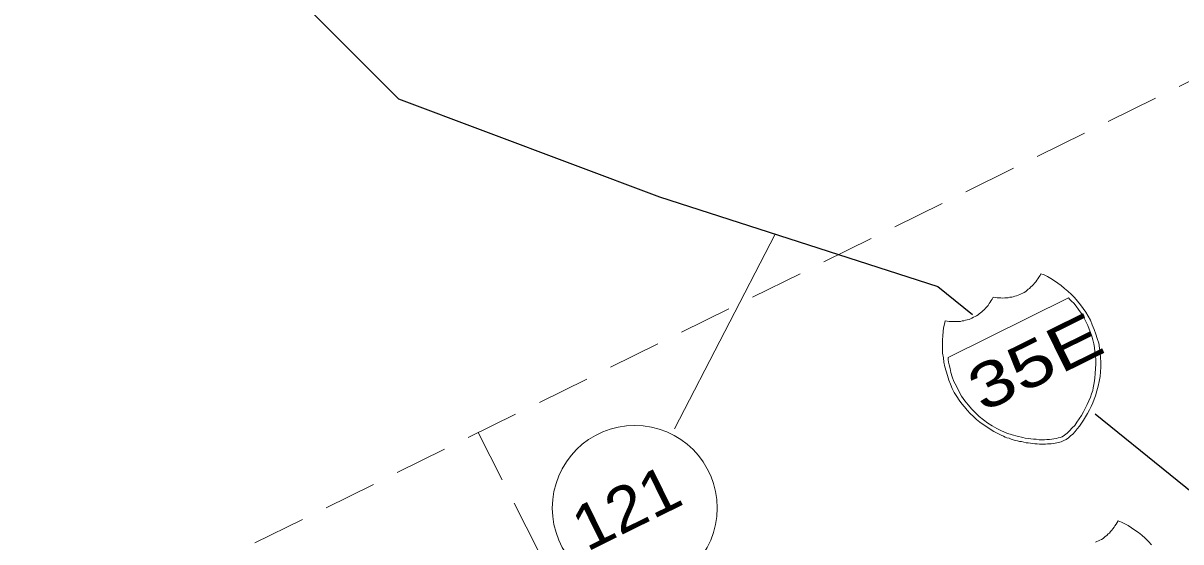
# Model space of a CAD drawing. Extents: x 2356606 to 2371222, y 6973096 to 6982644.
# Drawn here: x 2370920.3 to 2371051.8, y 6980586.9 to 6980645.7 of the extents above; entities that cross this region are included whole.
import ezdxf

# ---------------------------------------------------------------- set-up
doc = ezdxf.new("R2010")
doc.units = 0
doc.header["$LTSCALE"] = 2
doc.linetypes.add('MEDIUM_DASHED', pattern=[4.5, 3, -1.5])
doc.layers.add('62', color=7, linetype='Continuous', lineweight=13)
doc.layers.add('63', color=7, linetype='Continuous', lineweight=13)

msp = doc.modelspace()

# ---------------------------------------------------------------- linework, layer by layer
at = {"layer": '62', "linetype": 'MEDIUM_DASHED'}
for p, q in [((2371056.951, 6980641.227), (2370654.977, 6980442.841)), ((2370972, 6980599.301), (2371099.701, 6980348.989))]:
    msp.add_line(p, q, dxfattribs=at)
at = {"layer": '62'}
msp.add_line((2370994.27, 6980599.729), (2371005.707, 6980621.809), dxfattribs=at)
at = {"layer": '62', "lineweight": 25}
for points in [[(2370920.544, 6980679.674), (2370936.659, 6980663.489), (2370962.929, 6980637.158), (2370992.577, 6980626.045), (2371024.155, 6980615.857), (2371028.102, 6980612.689)], [(2371042.013, 6980601.435), (2371059.037, 6980587.681), (2371082.073, 6980558.75), (2371107.466, 6980541.874)]]:
    msp.add_lwpolyline(points, dxfattribs=at)
at = {"layer": '62'}
for points in [[(2371031.333, 6980614.584), (2371031.542, 6980614.563), (2371031.765, 6980614.572), (2371031.937, 6980614.581), (2371032.158, 6980614.59), (2371032.35, 6980614.658), (2371032.551, 6980614.657), (2371032.721, 6980614.718), (2371032.923, 6980614.765), (2371033.106, 6980614.807), (2371033.297, 6980614.875), (2371033.458, 6980614.955), (2371033.64, 6980615.044), (2371033.8, 6980615.122), (2371033.963, 6980615.203), (2371034.153, 6980615.324), (2371034.275, 6980615.434), (2371034.416, 6980615.554), (2371034.587, 6980615.664), (2371034.731, 6980615.833), (2371034.882, 6980615.934), (2371035.023, 6980616.104), (2371035.157, 6980616.244), (2371035.276, 6980616.405), (2371035.388, 6980616.586), (2371035.511, 6980616.747), (2371035.642, 6980616.935), (2371035.773, 6980617.126), (2371035.874, 6980617.327), (2371036.245, 6980617.185), (2371036.616, 6980616.991), (2371037, 6980616.777), (2371037.401, 6980616.525), (2371037.781, 6980616.261), (2371038.171, 6980615.976), (2371038.554, 6980615.662), (2371038.935, 6980615.35), (2371039.324, 6980614.964), (2371039.677, 6980614.611), (2371040.024, 6980614.206), (2371040.355, 6980613.793), (2371040.665, 6980613.369), (2371040.975, 6980612.944), (2371041.214, 6980612.509), (2371041.482, 6980612.066), (2371041.689, 6980611.541), (2371041.931, 6980611.006), (2371042.089, 6980610.482), (2371042.269, 6980609.969), (2371042.426, 6980609.443), (2371042.504, 6980608.879), (2371042.581, 6980608.364), (2371042.649, 6980607.82), (2371042.665, 6980607.277), (2371042.662, 6980606.723), (2371042.621, 6980606.2), (2371042.578, 6980605.678), (2371042.484, 6980605.104), (2371042.372, 6980604.573), (2371042.228, 6980604.05), (2371042.054, 6980603.486), (2371041.921, 6980603.096), (2371041.777, 6980602.673), (2371041.574, 6980602.272), (2371041.39, 6980601.88), (2371041.169, 6980601.469), (2371040.936, 6980601.078), (2371040.711, 6980600.716), (2371040.487, 6980600.356), (2371040.244, 6980600.036), (2371040.001, 6980599.715), (2371039.748, 6980599.414), (2371039.484, 6980599.132), (2371039.231, 6980598.934), (2371038.99, 6980598.712), (2371038.728, 6980598.534), (2371038.484, 6980598.413)], [(2371038.484, 6980598.413), (2371038.323, 6980598.334), (2371038.183, 6980598.264), (2371038.002, 6980598.224), (2371037.851, 6980598.174), (2371037.669, 6980598.136), (2371037.487, 6980598.097), (2371037.257, 6980598.057), (2371037.046, 6980598.029), (2371036.842, 6980598.03), (2371036.621, 6980598.021), (2371036.379, 6980598.001), (2371036.158, 6980597.992), (2371035.915, 6980597.974), (2371035.707, 6980597.995), (2371035.446, 6980598.018), (2371035.193, 6980598.019), (2371034.95, 6980598.05), (2371034.679, 6980598.092), (2371034.439, 6980598.123), (2371034.197, 6980598.153), (2371033.945, 6980598.206), (2371033.683, 6980598.277), (2371033.444, 6980598.31), (2371033.211, 6980598.369), (2371032.96, 6980598.422), (2371032.729, 6980598.483), (2371032.488, 6980598.565), (2371032.267, 6980598.657), (2371032.015, 6980598.709), (2371031.805, 6980598.779), (2371031.603, 6980598.88), (2371031.373, 6980598.994), (2371030.972, 6980599.196), (2371030.529, 6980599.43), (2371030.119, 6980599.704), (2371029.727, 6980599.938), (2371029.316, 6980600.211), (2371028.926, 6980600.494), (2371028.553, 6980600.789), (2371028.203, 6980601.143), (2371027.845, 6980601.466), (2371027.513, 6980601.831), (2371027.203, 6980602.206), (2371026.893, 6980602.581), (2371026.572, 6980602.974), (2371026.313, 6980603.399), (2371026.032, 6980603.863), (2371025.784, 6980604.316), (2371025.596, 6980604.801), (2371025.416, 6980605.265), (2371025.248, 6980605.76), (2371025.099, 6980606.264), (2371024.972, 6980606.777), (2371024.864, 6980607.301), (2371024.795, 6980607.794), (2371024.709, 6980608.329), (2371024.711, 6980608.832), (2371024.695, 6980609.325), (2371024.706, 6980609.806), (2371024.728, 6980610.271), (2371024.791, 6980610.753), (2371024.813, 6980611.166), (2371024.906, 6980611.586), (2371025.018, 6980611.97), (2371025.242, 6980611.928), (2371025.471, 6980611.915), (2371025.703, 6980611.906), (2371025.904, 6980611.905), (2371026.136, 6980611.892), (2371026.336, 6980611.893), (2371026.547, 6980611.921), (2371026.749, 6980611.92), (2371026.92, 6980611.98), (2371027.121, 6980611.979), (2371027.315, 6980612.048), (2371027.498, 6980612.087), (2371027.718, 6980612.148), (2371027.868, 6980612.196), (2371028.03, 6980612.276), (2371028.232, 6980612.376), (2371028.394, 6980612.456), (2371028.555, 6980612.535), (2371028.728, 6980612.646), (2371028.867, 6980612.765), (2371029.008, 6980612.883), (2371029.16, 6980612.986), (2371029.323, 6980613.166), (2371029.475, 6980613.266), (2371029.597, 6980613.424), (2371029.728, 6980613.567), (2371029.872, 6980613.736), (2371030, 6980613.927), (2371030.122, 6980614.087), (2371030.236, 6980614.268), (2371030.345, 6980614.448), (2371030.467, 6980614.659), (2371030.688, 6980614.617), (2371030.901, 6980614.596), (2371031.132, 6980614.585), (2371031.333, 6980614.584)], [(2371042.059, 6980586.855), (2371042.22, 6980586.934), (2371042.4, 6980587.023), (2371042.562, 6980587.102), (2371042.744, 6980587.193), (2371042.918, 6980587.302), (2371043.057, 6980587.421), (2371043.179, 6980587.531), (2371043.35, 6980587.642), (2371043.491, 6980587.812), (2371043.643, 6980587.912), (2371043.784, 6980588.081), (2371043.915, 6980588.223), (2371044.037, 6980588.383), (2371044.17, 6980588.574), (2371044.272, 6980588.723), (2371044.403, 6980588.915), (2371044.535, 6980589.104), (2371044.636, 6980589.306), (2371045.007, 6980589.16), (2371045.38, 6980588.97), (2371045.76, 6980588.756), (2371046.162, 6980588.502), (2371046.544, 6980588.238), (2371046.933, 6980587.956), (2371047.335, 6980587.651), (2371047.696, 6980587.327), (2371048.087, 6980586.942), (2371048.435, 6980586.589)]]:
    msp.add_lwpolyline(points, dxfattribs=at)
msp.add_lwpolyline([(2371038.99, 6980614.574), (2371025.328, 6980607.831), (2371025.348, 6980607.591), (2371025.388, 6980607.308), (2371025.446, 6980606.986), (2371025.555, 6980606.563), (2371025.653, 6980606.109), (2371025.791, 6980605.627), (2371025.998, 6980605.103), (2371026.27, 6980604.558), (2371026.545, 6980603.991), (2371026.867, 6980603.448), (2371027.227, 6980602.921), (2371027.616, 6980602.436), (2371028.018, 6980601.978), (2371028.428, 6980601.553), (2371028.867, 6980601.12), (2371029.351, 6980600.755), (2371029.83, 6980600.39), (2371030.32, 6980600.056), (2371030.863, 6980599.77), (2371031.404, 6980599.487), (2371031.997, 6980599.253), (2371032.6, 6980599.048), (2371033.185, 6980598.883), (2371033.807, 6980598.74), (2371034.099, 6980598.658), (2371034.413, 6980598.637), (2371034.713, 6980598.585), (2371035.044, 6980598.573), (2371035.337, 6980598.541), (2371035.659, 6980598.498), (2371035.96, 6980598.498), (2371036.262, 6980598.496), (2371036.554, 6980598.515), (2371036.827, 6980598.523), (2371037.117, 6980598.54), (2371037.351, 6980598.582), (2371037.621, 6980598.64), (2371037.842, 6980598.697), (2371038.065, 6980598.757), (2371038.275, 6980598.837), (2371038.537, 6980599.017), (2371038.852, 6980599.246), (2371039.124, 6980599.507), (2371039.419, 6980599.827), (2371039.702, 6980600.117), (2371039.964, 6980600.5), (2371040.209, 6980600.87), (2371040.473, 6980601.253), (2371040.717, 6980601.672), (2371040.931, 6980602.105), (2371041.132, 6980602.506), (2371041.307, 6980602.916), (2371041.488, 6980603.308), (2371041.623, 6980603.7), (2371041.745, 6980604.063), (2371041.787, 6980604.384), (2371041.91, 6980604.947), (2371041.973, 6980605.48), (2371042.038, 6980606.013), (2371042.069, 6980606.556), (2371042.102, 6980607.049), (2371042.084, 6980607.542), (2371042.057, 6980608.004), (2371041.999, 6980608.478), (2371041.942, 6980608.951), (2371041.884, 6980609.376), (2371041.763, 6980609.818), (2371041.635, 6980610.231), (2371041.507, 6980610.646), (2371041.357, 6980611.049), (2371041.187, 6980611.442), (2371040.999, 6980611.828), (2371040.73, 6980612.373), (2371040.441, 6980612.855), (2371040.139, 6980613.26), (2371039.88, 6980613.634), (2371039.59, 6980613.969), (2371039.351, 6980614.199), (2371039.151, 6980614.402)], close=True, dxfattribs=at)
msp.add_circle((2370989.769, 6980590.747), 9.364, dxfattribs=at)
at = {"layer": '63', "linetype": 'MEDIUM_DASHED'}
for p, q in [((2371056.951, 6980641.227), (2370654.977, 6980442.841)), ((2370972, 6980599.301), (2371099.701, 6980348.989))]:
    msp.add_line(p, q, dxfattribs=at)
at = {"layer": '63'}
msp.add_line((2370994.27, 6980599.729), (2371005.707, 6980621.809), dxfattribs=at)
at = {"layer": '63', "lineweight": 25}
for points in [[(2370920.544, 6980679.674), (2370936.659, 6980663.489), (2370962.929, 6980637.158), (2370992.577, 6980626.045), (2371024.155, 6980615.857), (2371028.102, 6980612.689)], [(2371042.013, 6980601.435), (2371059.037, 6980587.681), (2371082.073, 6980558.75), (2371107.466, 6980541.874)]]:
    msp.add_lwpolyline(points, dxfattribs=at)
at = {"layer": '63'}
for points in [[(2371031.333, 6980614.584), (2371031.542, 6980614.563), (2371031.765, 6980614.572), (2371031.937, 6980614.581), (2371032.158, 6980614.59), (2371032.35, 6980614.658), (2371032.551, 6980614.657), (2371032.721, 6980614.718), (2371032.923, 6980614.765), (2371033.106, 6980614.807), (2371033.297, 6980614.875), (2371033.458, 6980614.955), (2371033.64, 6980615.044), (2371033.8, 6980615.122), (2371033.963, 6980615.203), (2371034.153, 6980615.324), (2371034.275, 6980615.434), (2371034.416, 6980615.554), (2371034.587, 6980615.664), (2371034.731, 6980615.833), (2371034.882, 6980615.934), (2371035.023, 6980616.104), (2371035.157, 6980616.244), (2371035.276, 6980616.405), (2371035.388, 6980616.586), (2371035.511, 6980616.747), (2371035.642, 6980616.935), (2371035.773, 6980617.126), (2371035.874, 6980617.327), (2371036.245, 6980617.185), (2371036.616, 6980616.991), (2371037, 6980616.777), (2371037.401, 6980616.525), (2371037.781, 6980616.261), (2371038.171, 6980615.976), (2371038.554, 6980615.662), (2371038.935, 6980615.35), (2371039.324, 6980614.964), (2371039.677, 6980614.611), (2371040.024, 6980614.206), (2371040.355, 6980613.793), (2371040.665, 6980613.369), (2371040.975, 6980612.944), (2371041.214, 6980612.509), (2371041.482, 6980612.066), (2371041.689, 6980611.541), (2371041.931, 6980611.006), (2371042.089, 6980610.482), (2371042.269, 6980609.969), (2371042.426, 6980609.443), (2371042.504, 6980608.879), (2371042.581, 6980608.364), (2371042.649, 6980607.82), (2371042.665, 6980607.277), (2371042.662, 6980606.723), (2371042.621, 6980606.2), (2371042.578, 6980605.678), (2371042.484, 6980605.104), (2371042.372, 6980604.573), (2371042.228, 6980604.05), (2371042.054, 6980603.486), (2371041.921, 6980603.096), (2371041.777, 6980602.673), (2371041.574, 6980602.272), (2371041.39, 6980601.88), (2371041.169, 6980601.469), (2371040.936, 6980601.078), (2371040.711, 6980600.716), (2371040.487, 6980600.356), (2371040.244, 6980600.036), (2371040.001, 6980599.715), (2371039.748, 6980599.414), (2371039.484, 6980599.132), (2371039.231, 6980598.934), (2371038.99, 6980598.712), (2371038.728, 6980598.534), (2371038.484, 6980598.413)], [(2371038.484, 6980598.413), (2371038.323, 6980598.334), (2371038.183, 6980598.264), (2371038.002, 6980598.224), (2371037.851, 6980598.174), (2371037.669, 6980598.136), (2371037.487, 6980598.097), (2371037.257, 6980598.057), (2371037.046, 6980598.029), (2371036.842, 6980598.03), (2371036.621, 6980598.021), (2371036.379, 6980598.001), (2371036.158, 6980597.992), (2371035.915, 6980597.974), (2371035.707, 6980597.995), (2371035.446, 6980598.018), (2371035.193, 6980598.019), (2371034.95, 6980598.05), (2371034.679, 6980598.092), (2371034.439, 6980598.123), (2371034.197, 6980598.153), (2371033.945, 6980598.206), (2371033.683, 6980598.277), (2371033.444, 6980598.31), (2371033.211, 6980598.369), (2371032.96, 6980598.422), (2371032.729, 6980598.483), (2371032.488, 6980598.565), (2371032.267, 6980598.657), (2371032.015, 6980598.709), (2371031.805, 6980598.779), (2371031.603, 6980598.88), (2371031.373, 6980598.994), (2371030.972, 6980599.196), (2371030.529, 6980599.43), (2371030.119, 6980599.704), (2371029.727, 6980599.938), (2371029.316, 6980600.211), (2371028.926, 6980600.494), (2371028.553, 6980600.789), (2371028.203, 6980601.143), (2371027.845, 6980601.466), (2371027.513, 6980601.831), (2371027.203, 6980602.206), (2371026.893, 6980602.581), (2371026.572, 6980602.974), (2371026.313, 6980603.399), (2371026.032, 6980603.863), (2371025.784, 6980604.316), (2371025.596, 6980604.801), (2371025.416, 6980605.265), (2371025.248, 6980605.76), (2371025.099, 6980606.264), (2371024.972, 6980606.777), (2371024.864, 6980607.301), (2371024.795, 6980607.794), (2371024.709, 6980608.329), (2371024.711, 6980608.832), (2371024.695, 6980609.325), (2371024.706, 6980609.806), (2371024.728, 6980610.271), (2371024.791, 6980610.753), (2371024.813, 6980611.166), (2371024.906, 6980611.586), (2371025.018, 6980611.97), (2371025.242, 6980611.928), (2371025.471, 6980611.915), (2371025.703, 6980611.906), (2371025.904, 6980611.905), (2371026.136, 6980611.892), (2371026.336, 6980611.893), (2371026.547, 6980611.921), (2371026.749, 6980611.92), (2371026.92, 6980611.98), (2371027.121, 6980611.979), (2371027.315, 6980612.048), (2371027.498, 6980612.087), (2371027.718, 6980612.148), (2371027.868, 6980612.196), (2371028.03, 6980612.276), (2371028.232, 6980612.376), (2371028.394, 6980612.456), (2371028.555, 6980612.535), (2371028.728, 6980612.646), (2371028.867, 6980612.765), (2371029.008, 6980612.883), (2371029.16, 6980612.986), (2371029.323, 6980613.166), (2371029.475, 6980613.266), (2371029.597, 6980613.424), (2371029.728, 6980613.567), (2371029.872, 6980613.736), (2371030, 6980613.927), (2371030.122, 6980614.087), (2371030.236, 6980614.268), (2371030.345, 6980614.448), (2371030.467, 6980614.659), (2371030.688, 6980614.617), (2371030.901, 6980614.596), (2371031.132, 6980614.585), (2371031.333, 6980614.584)], [(2371042.059, 6980586.855), (2371042.22, 6980586.934), (2371042.4, 6980587.023), (2371042.562, 6980587.102), (2371042.744, 6980587.193), (2371042.918, 6980587.302), (2371043.057, 6980587.421), (2371043.179, 6980587.531), (2371043.35, 6980587.642), (2371043.491, 6980587.812), (2371043.643, 6980587.912), (2371043.784, 6980588.081), (2371043.915, 6980588.223), (2371044.037, 6980588.383), (2371044.17, 6980588.574), (2371044.272, 6980588.723), (2371044.403, 6980588.915), (2371044.535, 6980589.104), (2371044.636, 6980589.306), (2371045.007, 6980589.16), (2371045.38, 6980588.97), (2371045.76, 6980588.756), (2371046.162, 6980588.502), (2371046.544, 6980588.238), (2371046.933, 6980587.956), (2371047.335, 6980587.651), (2371047.696, 6980587.327), (2371048.087, 6980586.942), (2371048.435, 6980586.589)]]:
    msp.add_lwpolyline(points, dxfattribs=at)
msp.add_lwpolyline([(2371038.99, 6980614.574), (2371025.328, 6980607.831), (2371025.348, 6980607.591), (2371025.388, 6980607.308), (2371025.446, 6980606.986), (2371025.555, 6980606.563), (2371025.653, 6980606.109), (2371025.791, 6980605.627), (2371025.998, 6980605.103), (2371026.27, 6980604.558), (2371026.545, 6980603.991), (2371026.867, 6980603.448), (2371027.227, 6980602.921), (2371027.616, 6980602.436), (2371028.018, 6980601.978), (2371028.428, 6980601.553), (2371028.867, 6980601.12), (2371029.351, 6980600.755), (2371029.83, 6980600.39), (2371030.32, 6980600.056), (2371030.863, 6980599.77), (2371031.404, 6980599.487), (2371031.997, 6980599.253), (2371032.6, 6980599.048), (2371033.185, 6980598.883), (2371033.807, 6980598.74), (2371034.099, 6980598.658), (2371034.413, 6980598.637), (2371034.713, 6980598.585), (2371035.044, 6980598.573), (2371035.337, 6980598.541), (2371035.659, 6980598.498), (2371035.96, 6980598.498), (2371036.262, 6980598.496), (2371036.554, 6980598.515), (2371036.827, 6980598.523), (2371037.117, 6980598.54), (2371037.351, 6980598.582), (2371037.621, 6980598.64), (2371037.842, 6980598.697), (2371038.065, 6980598.757), (2371038.275, 6980598.837), (2371038.537, 6980599.017), (2371038.852, 6980599.246), (2371039.124, 6980599.507), (2371039.419, 6980599.827), (2371039.702, 6980600.117), (2371039.964, 6980600.5), (2371040.209, 6980600.87), (2371040.473, 6980601.253), (2371040.717, 6980601.672), (2371040.931, 6980602.105), (2371041.132, 6980602.506), (2371041.307, 6980602.916), (2371041.488, 6980603.308), (2371041.623, 6980603.7), (2371041.745, 6980604.063), (2371041.787, 6980604.384), (2371041.91, 6980604.947), (2371041.973, 6980605.48), (2371042.038, 6980606.013), (2371042.069, 6980606.556), (2371042.102, 6980607.049), (2371042.084, 6980607.542), (2371042.057, 6980608.004), (2371041.999, 6980608.478), (2371041.942, 6980608.951), (2371041.884, 6980609.376), (2371041.763, 6980609.818), (2371041.635, 6980610.231), (2371041.507, 6980610.646), (2371041.357, 6980611.049), (2371041.187, 6980611.442), (2371040.999, 6980611.828), (2371040.73, 6980612.373), (2371040.441, 6980612.855), (2371040.139, 6980613.26), (2371039.88, 6980613.634), (2371039.59, 6980613.969), (2371039.351, 6980614.199), (2371039.151, 6980614.402)], close=True, dxfattribs=at)
msp.add_circle((2370989.769, 6980590.747), 9.364, dxfattribs=at)

# ---------------------------------------------------------------- texts
at = {"layer": '62'}
for s, width, p in [('35E', 1.3, (2371029.262, 6980601.542)), ('121', 1.1, (2370984.316, 6980585.736))]:
    msp.add_text(s, height=5.099, rotation=26.268, dxfattribs=dict(at, width=width)).set_placement(p)
at = {"layer": '63'}
for s, width, p in [('35E', 1.3, (2371029.262, 6980601.542)), ('121', 1.1, (2370984.316, 6980585.736))]:
    msp.add_text(s, height=5.099, rotation=26.268, dxfattribs=dict(at, width=width)).set_placement(p)

doc.saveas('drawing.dxf')
